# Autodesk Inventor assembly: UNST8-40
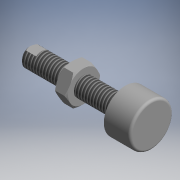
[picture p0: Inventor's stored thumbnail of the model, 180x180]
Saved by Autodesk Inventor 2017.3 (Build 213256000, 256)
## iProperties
Category: PARTsolutions
Company: MISUMI
Part Number: UNST8-40
Catalog Web Link: www.cadenas.de
Description: UNST-Shock Absorption Stoppers -Screws with Low Elastic Rubber-
Vendor: MISUMI
Document SubType Name: Assembly
Designer: partserver
Manufacturer: MISUMI
Mass: 5.31279 g
Surface Area: 26.2325 cm^2
Volume: 5.31279 cm^3
Density: 1 g/cm^3
Title: UNST8-40
Author: Cadenas PARTsolutions
Comments: Shock Absorption Stoppers -Screws with Low Elastic Rubber-
PSOL_IDENT_0: {$CADENAS_DATA\23d-libs\misumi\metric\15_locating_components\unst_asmtab.prj},161 {VTYP=3D},{STYP=AS
PSOL_IDENT_1: STAB},{NB=UNST8-40},{LINA=UNST8-40},{NN=UNST},{DATE=02.06.2021 05:59:50},{GEOMDATE=21.02.2011},{VERS
PSOL_IDENT_2: ION=},{LINEID=50},{WBVAR=L},{WBNUMERIC=L}  {NB=UNST8-40},{LINA=UNST8-40},{KT=DUMMY},{PN=UNST8-40},{T
PSOL_IDENT_3: YPE=UNST},{MATS=Low Elastic Rubber(HanenaitoR RGP-60L)},{HARDS=Shore A57},{MATB=304 Stainless Steel}
PSOL_IDENT_4: ,{AC=304 Stainless Steel},{M=8},{MMIN=6.647},{L=40},{L1=30,'30',40,'40',50,'50'},{TT=5.7},{C=18},{D=
PSOL_IDENT_5: 14.40},{B=13.0},{H=11},{E=5.3},{MM=5.0},{W=6.5},{PPATH=unst_templ.prj}
NB: UNST8-40
NN: UNST
NT: Shock Absorption Stoppers -Screws with Low Elastic Rubber-
NBSYN: $PN.
LINA: UNST8-40
CATALOG: Misumi
PN: UNST8-40
MATS: Low Elastic Rubber(HanenaitoR RGP-60L)
HARDS: Shore A57
MATB: 304 Stainless Steel
AC: 304 Stainless Steel
M: 8
L: 40
TT: 5.7
C: 18
D: 14.4
B: 13
H: 11
E: 5.3
MM: 5
W: 6.5
SUPPLIER: MISUMI
ARTICLENO: UNST8-40
BOMINFO: UNST8-40
CREATOR: CADENAS GmbH
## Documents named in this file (3)
- e:\temp\worker_34\temp\exporttempdir_608_78_oV2fP\format_0\UNST8-40.iam
- e:\temp\worker_34\temp\exporttempdir_608_78_oV2fP\format_0\UNST8-40_b.ipt
- e:\temp\worker_34\temp\exporttempdir_608_78_oV2fP\format_0\SLBNR-8_n.ipt
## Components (2 placed, 2 different names)
1. UNST8-40_b:1 — unstb_n_Z@1 <-> n_b_Z@2
2. SLBNR-8_n:1 — unstb_n_Z@1 <-> n_b_Z@2
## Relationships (1: Mate 1)
- unstb_n_Z@1 <-> n_b_Z@2 [Mate]: UNST8-40_b:1 ↔ SLBNR-8_n:1
